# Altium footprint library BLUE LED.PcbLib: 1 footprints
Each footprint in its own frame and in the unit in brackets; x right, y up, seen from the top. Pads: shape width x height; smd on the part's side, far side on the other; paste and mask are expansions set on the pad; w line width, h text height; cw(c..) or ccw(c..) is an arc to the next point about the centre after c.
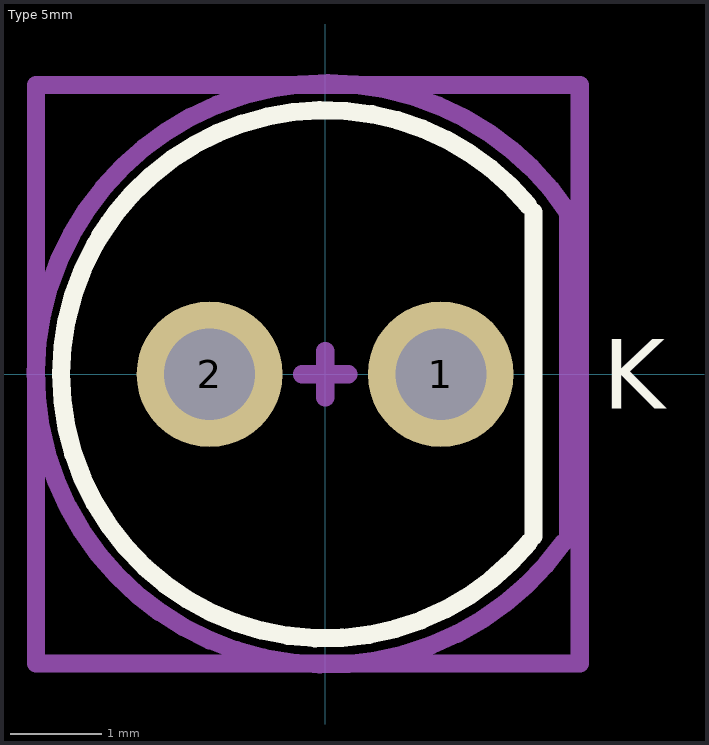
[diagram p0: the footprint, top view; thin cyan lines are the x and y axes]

## Type 5mm [mm] "THT, LED-5mm, 2pin- Body 5.8mm"
height 12.1
pads (2):
  round 1.6 hole 1: 1(1.27,0) 2(-1.27,0)
Top Overlay:
  lines w0.2: -2.47,1.52 cw(c0,0) 2.228,1.857 ; -2.369,1.672 ccw(c0,0) 2.239,-1.844 ; 2.286,-1.778 2.286,1.778
  text "K" at 3.048,-0.381 h0.76
Mechanical 13:
  lines w0.2: -3.175,-3.175 2.794,-3.175 2.794,3.175 -3.175,3.175 -3.175,-3.175
Mechanical 15:
  lines w0.2: -0.254,0 0.254,0 ; 0,-0.254 0,0.254 ; 2.616,-1.846 cw(c0.014,0.003) 2.667,1.778 2.667,-1.778
  text ".Designator" at 0,0 h0.76
  text "K" at 3.048,-0.381 h0.76
3D body "WL-TMRW_5mm.stp": height 11.7, standoff -23.3, extent -2.9,-2.9 2.5,2.9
